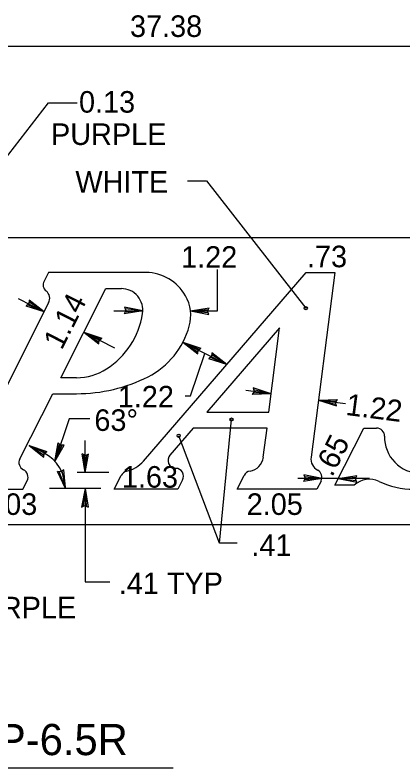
# Model space of a CAD drawing. Extents: x 10268197 to 10269179, y 2141503 to 2142677.
# Drawn here: x 10268612.19 to 10268622.88, y 2142145.29 to 2142166.05 of the extents above; entities that cross this region are included whole.
import ezdxf

# ---------------------------------------------------------------- set-up
doc = ezdxf.new("R2010")
doc.units = 0
for name, color, linetype in [('1', 7, 'Continuous'), ('21', 7, 'Continuous'), ('Default', 7, 'Continuous')]:
    doc.layers.add(name, color=color, linetype=linetype)

msp = doc.modelspace()

# ---------------------------------------------------------------- linework, layer by layer
at = {"layer": '1'}
for p, q in [((10268596.269, 2142165.194), (10268617.622, 2142165.194)), ((10268617.622, 2142165.194), (10268636.689, 2142165.194)), ((10268611.389, 2142161.404), (10268613.109, 2142163.626)), ((10268613.109, 2142163.626), (10268613.904, 2142163.626)), ((10268616.94, 2142161.481), (10268617.463, 2142161.481)), ((10268617.463, 2142161.481), (10268620.203, 2142157.967)), ((10268617.771, 2142157.895), (10268617.771, 2142159.036)), ((10268612.272, 2142158.229), (10268612.99, 2142157.862)), ((10268612.572, 2142158.085), (10268612.495, 2142158.023)), ((10268612.58, 2142158.183), (10268612.572, 2142158.085)), ((10268612.99, 2142157.862), (10268612.575, 2142158.132)), ((10268612.99, 2142157.862), (10268612.58, 2142158.183)), ((10268612.99, 2142157.862), (10268612.495, 2142158.023)), ((10268612.99, 2142157.862), (10268612.536, 2142158.055)), ((10268614.909, 2142157.895), (10268615.716, 2142157.895)), ((10268615.243, 2142157.903), (10268615.202, 2142157.813)), ((10268615.716, 2142157.895), (10268615.202, 2142157.813)), ((10268615.716, 2142157.895), (10268615.205, 2142157.994)), ((10268615.205, 2142157.994), (10268615.243, 2142157.903)), ((10268615.716, 2142157.895), (10268615.223, 2142157.86)), ((10268615.716, 2142157.895), (10268615.225, 2142157.946)), ((10268617.023, 2142157.895), (10268617.538, 2142157.976)), ((10268617.023, 2142157.895), (10268617.516, 2142157.929)), ((10268617.023, 2142157.895), (10268617.771, 2142157.895)), ((10268617.023, 2142157.895), (10268617.534, 2142157.795)), ((10268617.023, 2142157.895), (10268617.515, 2142157.844)), ((10268617.497, 2142157.887), (10268617.538, 2142157.976)), ((10268617.534, 2142157.795), (10268617.497, 2142157.887)), ((10268614.088, 2142157.304), (10268614.934, 2142156.873)), ((10268614.088, 2142157.304), (10268614.583, 2142157.144)), ((10268614.088, 2142157.304), (10268614.498, 2142156.984)), ((10268614.088, 2142157.304), (10268614.502, 2142157.036)), ((10268614.088, 2142157.304), (10268614.542, 2142157.111)), ((10268614.498, 2142156.984), (10268614.505, 2142157.083)), ((10268614.505, 2142157.083), (10268614.583, 2142157.144)), ((10268616.815, 2142157.029), (10268618.028, 2142156.411)), ((10268616.815, 2142157.029), (10268617.31, 2142156.868)), ((10268616.815, 2142157.029), (10268617.226, 2142156.709)), ((10268616.815, 2142157.029), (10268617.23, 2142156.761)), ((10268616.815, 2142157.029), (10268617.269, 2142156.836)), ((10268617.233, 2142156.807), (10268617.31, 2142156.868)), ((10268617.226, 2142156.709), (10268617.233, 2142156.807)), ((10268619.248, 2142155.604), (10268618.55, 2142155.696)), ((10268618.779, 2142155.674), (10268618.727, 2142155.59)), ((10268619.248, 2142155.604), (10268618.727, 2142155.59)), ((10268619.248, 2142155.604), (10268618.754, 2142155.769)), ((10268618.754, 2142155.769), (10268618.779, 2142155.674)), ((10268619.248, 2142155.604), (10268618.755, 2142155.634)), ((10268619.248, 2142155.604), (10268618.767, 2142155.719)), ((10268620.555, 2142155.435), (10268621.075, 2142155.45)), ((10268620.555, 2142155.435), (10268621.3, 2142155.339)), ((10268620.555, 2142155.435), (10268621.048, 2142155.271)), ((10268620.555, 2142155.435), (10268621.036, 2142155.322)), ((10268620.555, 2142155.435), (10268621.047, 2142155.406)), ((10268621.023, 2142155.367), (10268621.075, 2142155.45)), ((10268621.048, 2142155.271), (10268621.023, 2142155.367)), ((10268613.684, 2142154.917), (10268613.286, 2142153.742)), ((10268614.249, 2142154.917), (10268613.684, 2142154.917)), ((10268617.829, 2142151.487), (10268618.157, 2142154.898)), ((10268617.829, 2142151.487), (10268616.701, 2142154.449)), ((10268612.979, 2142153.974), (10268612.575, 2142154.18)), ((10268612.575, 2142154.18), (10268613.07, 2142154.019)), ((10268612.575, 2142154.18), (10268612.985, 2142153.86)), ((10268612.575, 2142154.18), (10268612.989, 2142153.911)), ((10268612.575, 2142154.18), (10268613.029, 2142153.987)), ((10268613.286, 2142153.742), (10268613.374, 2142154.255)), ((10268613.286, 2142153.742), (10268613.412, 2142154.219)), ((10268613.286, 2142153.742), (10268613.544, 2142154.194)), ((10268613.286, 2142153.742), (10268613.493, 2142154.191)), ((10268613.446, 2142154.188), (10268613.374, 2142154.255)), ((10268613.544, 2142154.194), (10268613.446, 2142154.188)), ((10268614.12, 2142153.435), (10268614.12, 2142154.314)), ((10268612.985, 2142153.86), (10268612.993, 2142153.958)), ((10268612.993, 2142153.958), (10268613.07, 2142154.019)), ((10268614.12, 2142153.435), (10268614.038, 2142153.949)), ((10268614.128, 2142153.908), (10268614.038, 2142153.949)), ((10268614.12, 2142153.435), (10268614.085, 2142153.927)), ((10268614.12, 2142153.435), (10268614.219, 2142153.946)), ((10268614.12, 2142153.435), (10268614.171, 2142153.926)), ((10268614.219, 2142153.946), (10268614.128, 2142153.908)), ((10268613.534, 2142153.514), (10268613.456, 2142153.453)), ((10268613.579, 2142152.996), (10268613.534, 2142153.514)), ((10268613.579, 2142152.996), (10268613.359, 2142153.467)), ((10268613.456, 2142153.453), (10268613.359, 2142153.467)), ((10268613.579, 2142152.996), (10268613.41, 2142153.46)), ((10268613.579, 2142152.996), (10268613.493, 2142153.482)), ((10268614.779, 2142153.435), (10268613.9, 2142153.435)), ((10268620.66, 2142153.27), (10268619.984, 2142153.27)), ((10268621.099, 2142153.27), (10268620.66, 2142153.27)), ((10268621.956, 2142153.27), (10268621.099, 2142153.27)), ((10268614.559, 2142152.996), (10268613.14, 2142152.996)), ((10268614.12, 2142152.996), (10268614.02, 2142152.485)), ((10268614.12, 2142152.996), (10268614.068, 2142152.505)), ((10268614.12, 2142152.996), (10268614.12, 2142150.418)), ((10268614.12, 2142152.996), (10268614.201, 2142152.482)), ((10268614.12, 2142152.996), (10268614.154, 2142152.504)), ((10268614.02, 2142152.485), (10268614.112, 2142152.523)), ((10268614.112, 2142152.523), (10268614.201, 2142152.482)), ((10268618.315, 2142151.487), (10268617.829, 2142151.487)), ((10268614.12, 2142150.418), (10268614.805, 2142150.418))]:
    msp.add_line(p, q, dxfattribs=at)
msp.add_lwpolyline([(10268616.88, 2142155.553), (10268617.028, 2142155.553), (10268617.422, 2142156.72)], dxfattribs=at)
for centre in [(10268620.203, 2142157.967), (10268618.157, 2142154.898), (10268616.701, 2142154.449)]:
    msp.add_circle(centre, 0.0439, dxfattribs=at)
msp.add_arc((10268612.48, 2142152.996), 1.098, 0, 62.9941, dxfattribs=at)
at = {"layer": '21'}
for p, q in [((10268617.609, 2142156.634), (10268617.532, 2142156.572)), ((10268618.028, 2142156.411), (10268617.573, 2142156.604)), ((10268617.617, 2142156.732), (10268617.609, 2142156.634)), ((10268618.028, 2142156.411), (10268617.613, 2142156.68)), ((10268618.028, 2142156.411), (10268617.617, 2142156.732)), ((10268618.028, 2142156.411), (10268617.532, 2142156.572)), ((10268620.66, 2142153.27), (10268620.149, 2142153.369)), ((10268620.149, 2142153.369), (10268620.186, 2142153.278)), ((10268620.66, 2142153.27), (10268620.168, 2142153.321)), ((10268621.099, 2142153.27), (10268621.614, 2142153.351)), ((10268621.099, 2142153.27), (10268621.592, 2142153.304)), ((10268621.573, 2142153.262), (10268621.614, 2142153.351)), ((10268620.186, 2142153.278), (10268620.145, 2142153.188)), ((10268620.66, 2142153.27), (10268620.145, 2142153.188)), ((10268620.66, 2142153.27), (10268620.167, 2142153.235)), ((10268621.099, 2142153.27), (10268621.611, 2142153.171)), ((10268621.099, 2142153.27), (10268621.591, 2142153.218)), ((10268621.611, 2142153.171), (10268621.573, 2142153.262)), ((10268606.71, 2142145.291), (10268616.551, 2142145.291))]:
    msp.add_line(p, q, dxfattribs=at)
at = {"layer": 'Default'}
for p, q in [((10268611.626, 2142159.916), (10268636.689, 2142159.916)), ((10268613.108, 2142158.949), (10268612.988, 2142158.713)), ((10268615.799, 2142158.949), (10268613.108, 2142158.949)), ((10268615.731, 2142153.75), (10268620.218, 2142158.949)), ((10268620.218, 2142158.949), (10268621.009, 2142158.949)), ((10268621.009, 2142158.949), (10268620.351, 2142153.856)), ((10268613.453, 2142156.05), (10268614.696, 2142158.507)), ((10268614.696, 2142158.507), (10268615.12, 2142158.507)), ((10268613.116, 2142158.113), (10268610.941, 2142153.811)), ((10268619.482, 2142157.422), (10268617.477, 2142155.098)), ((10268619.182, 2142155.098), (10268619.482, 2142157.422)), ((10268613.888, 2142156.05), (10268613.453, 2142156.05)), ((10268612.321, 2142153.812), (10268613.229, 2142155.608)), ((10268613.229, 2142155.608), (10268613.888, 2142155.608)), ((10268617.477, 2142155.098), (10268619.182, 2142155.098)), ((10268617.096, 2142154.656), (10268616.459, 2142153.917)), ((10268619.137, 2142154.656), (10268617.096, 2142154.656)), ((10268619.033, 2142153.856), (10268619.137, 2142154.656)), ((10268621.006, 2142153.085), (10268621.803, 2142154.662)), ((10268621.803, 2142154.662), (10268622.156, 2142154.662)), ((10268614.923, 2142152.974), (10268615.114, 2142153.352)), ((10268618.314, 2142152.974), (10268618.507, 2142153.358)), ((10268612.405, 2142152.974), (10268612.525, 2142153.21)), ((10268616.81, 2142153.23), (10268616.68, 2142152.974)), ((10268620.626, 2142153.202), (10268620.511, 2142152.974)), ((10268621.539, 2142153.085), (10268621.006, 2142153.085)), ((10268610.209, 2142152.974), (10268612.405, 2142152.974)), ((10268616.68, 2142152.974), (10268614.923, 2142152.974)), ((10268620.511, 2142152.974), (10268618.314, 2142152.974)), ((10268610.892, 2142152.007), (10268632.66, 2142152.007))]:
    msp.add_line(p, q, dxfattribs=at)
for centre, major_axis, start_param, end_param in [((10268615.799, 2142157.688), (0, 1.261), 5.226065, 6.283185), ((10268613.184, 2142158.613), (0, -0.221), 4.240773, 5.605302), ((10268615.119, 2142157.909), (0, -0.598), 1.415043, 3.141593), ((10268612.881, 2142158.233), (0, -0.266), 1.099604, 2.46371), ((10268615.933, 2142157.764), (0, 1.107), 4.445482, 5.226065), ((10268613.535, 2142158.16), (0, -2.213), 0.565847, 1.415043), ((10268614.873, 2142158.056), (0, -2.213), 0.465011, 1.30389), ((10268613.888, 2142157.599), (0, -1.549), 0, 0.565847), ((10268613.888, 2142160.034), (0, -4.426), 0, 0.465011), ((10268622.156, 2142154.441), (0, 0.221), 4.689114, 6.283185), ((10268623.364, 2142154.413), (0, 0.996), 1.547521, 3.141593), ((10268616.624, 2142153.773), (0, 0.221), 0.854904, 3.118676), ((10268612.516, 2142153.711), (0, 0.221), 1.099355, 2.701477), ((10268615.068, 2142154.332), (0, -0.885), 0.22194, 0.855152), ((10268618.598, 2142153.913), (0, -0.443), 0.161263, 1.440999), ((10268620.699, 2142153.81), (0, 0.354), 1.441439, 2.650585), ((10268612.329, 2142153.311), (0, 0.221), 4.241567, 5.84307), ((10268616.614, 2142153.33), (0, 0.221), 4.240773, 6.260268), ((10268620.43, 2142153.303), (0, 0.221), 4.240773, 5.792177), ((10268615.31, 2142153.252), (0, -0.221), 3.363532, 4.241567), ((10268618.703, 2142153.258), (0, -0.221), 3.302856, 4.241567), ((10268621.96, 2142152.633), (0, -0.62), 2.69443, 3.895387), ((10268623.176, 2142155.187), (0, -2.213), 5.836023, 6.283185)]:
    msp.add_ellipse(centre, major_axis=major_axis, ratio=0.992614, start_param=start_param, end_param=end_param, dxfattribs=at)

# ---------------------------------------------------------------- texts
at = {"layer": '1'}
for s, height, p in [('37.38', 0.5942, (10268615.359, 2142165.444)), ('0.13', 0.5942, (10268613.953, 2142163.357)), ('PURPLE', 0.5942, (10268613.182, 2142162.466)), ('WHITE', 0.5942, (10268613.854, 2142161.151)), ('1.22', 0.5942, (10268616.768, 2142159.081)), ('.73', 0.5942, (10268620.237, 2142159.095)), ('63°', 0.5942, (10268614.377, 2142154.583)), ('1.63', 0.5942, (10268615.135, 2142153.019)), ('2.03', 0.5942, (10268611.255, 2142152.267)), ('2.05', 0.5942, (10268618.575, 2142152.267)), ('.41', 0.5942, (10268618.704, 2142151.135)), ('.41 TYP', 0.5942, (10268615.05, 2142150.085)), ('PURPLE', 0.5942, (10268610.695, 2142149.416)), ('LOGO EP-6.5R', 0.86053, (10268607.305, 2142145.644))]:
    msp.add_text(s, height=height, dxfattribs=at).set_placement(p)
for s, rotation, p in [('1.14', 62.9907, (10268613.475, 2142156.792)), ('1.22', 360, (10268615.022, 2142155.229)), ('1.22', 352.5994, (10268621.286, 2142155.026)), ('.65', 63, (10268620.928, 2142153.289))]:
    msp.add_text(s, height=0.5942, rotation=rotation, dxfattribs=at).set_placement(p)

doc.saveas('drawing.dxf')
